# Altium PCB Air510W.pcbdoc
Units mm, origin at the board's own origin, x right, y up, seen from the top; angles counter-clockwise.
Board outline 24.2 x 23.82 mm, 4 copper layers (Top Layer, 内层 2, 内层 3, Bottom Layer); 1 components, 0 nets, 18 pads, 0 vias.
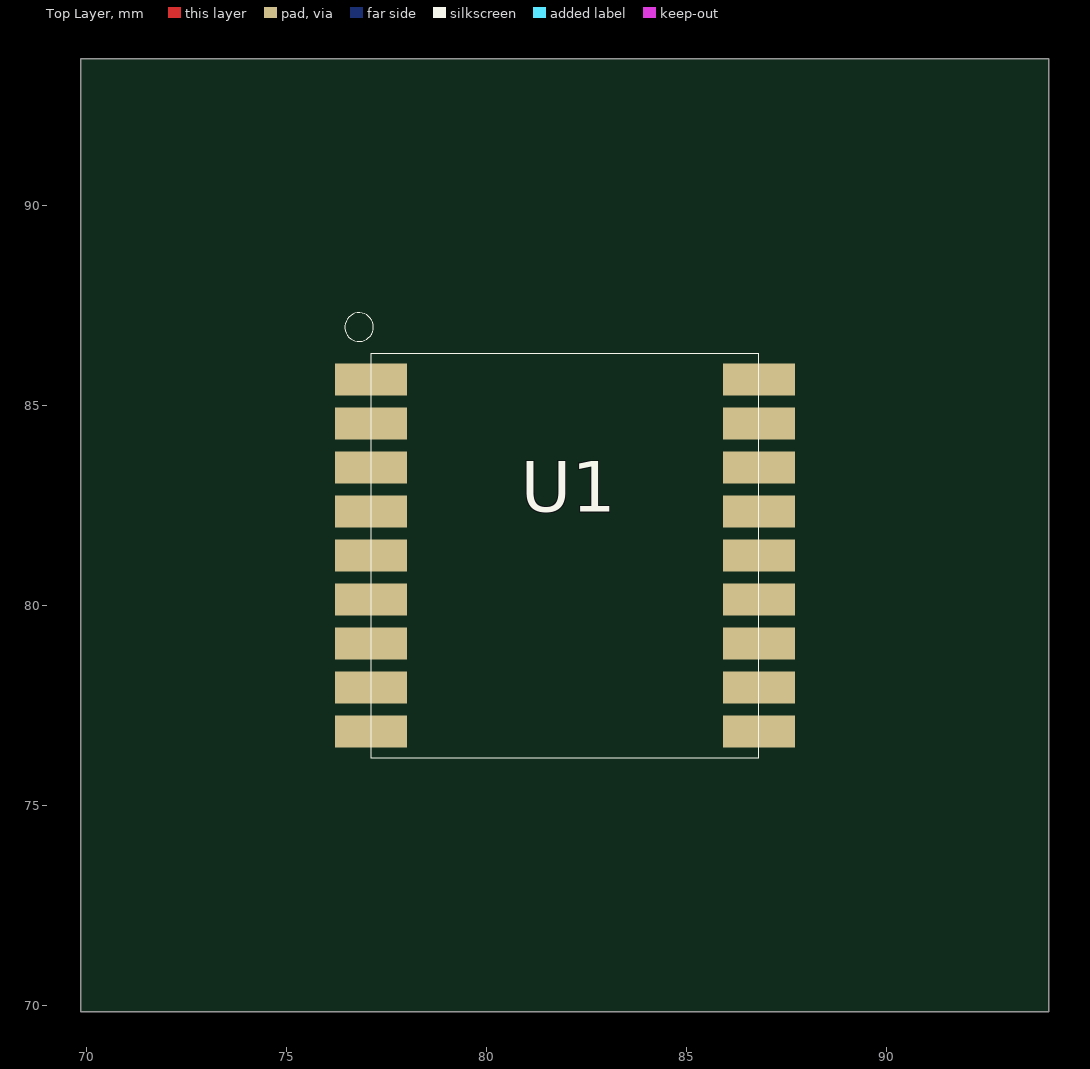
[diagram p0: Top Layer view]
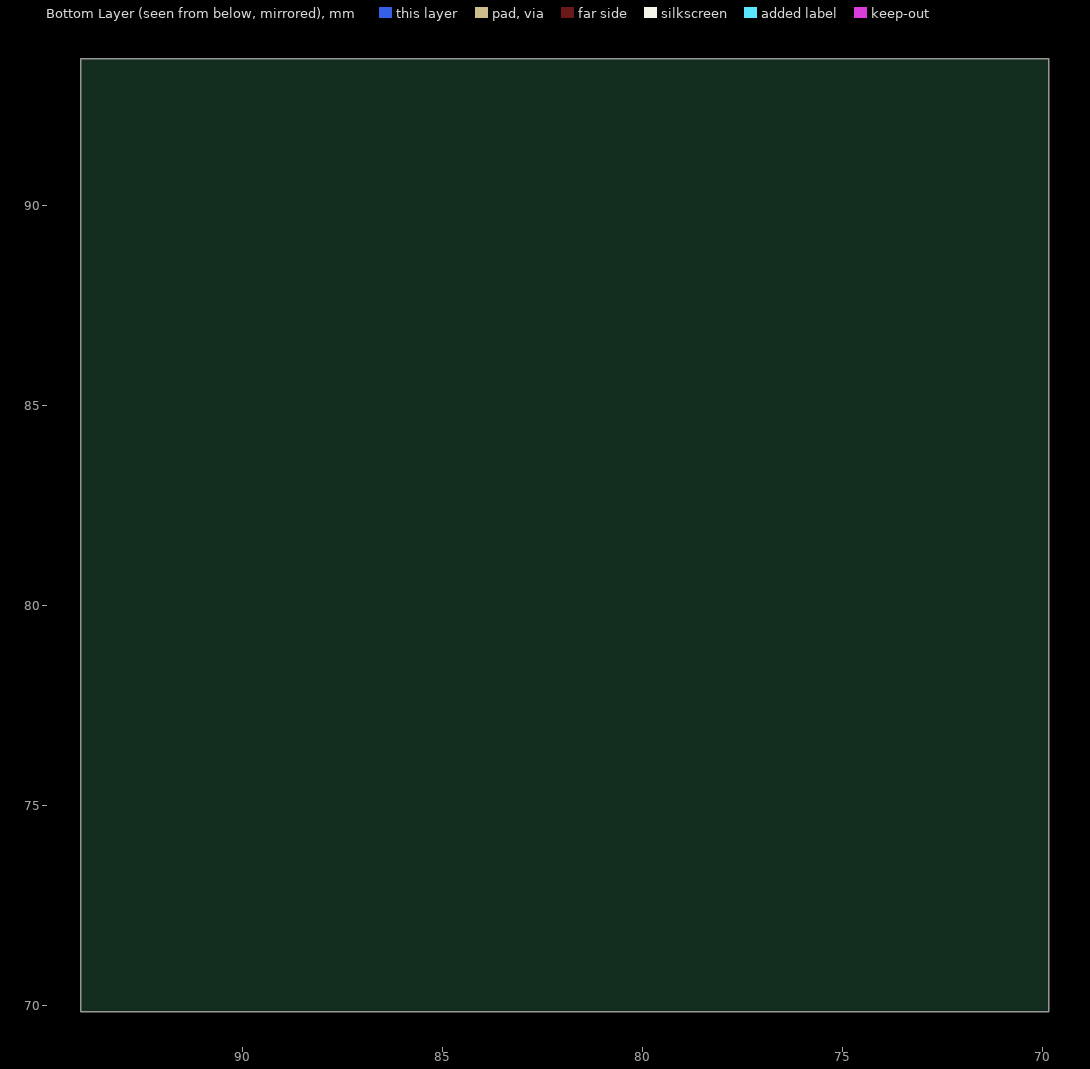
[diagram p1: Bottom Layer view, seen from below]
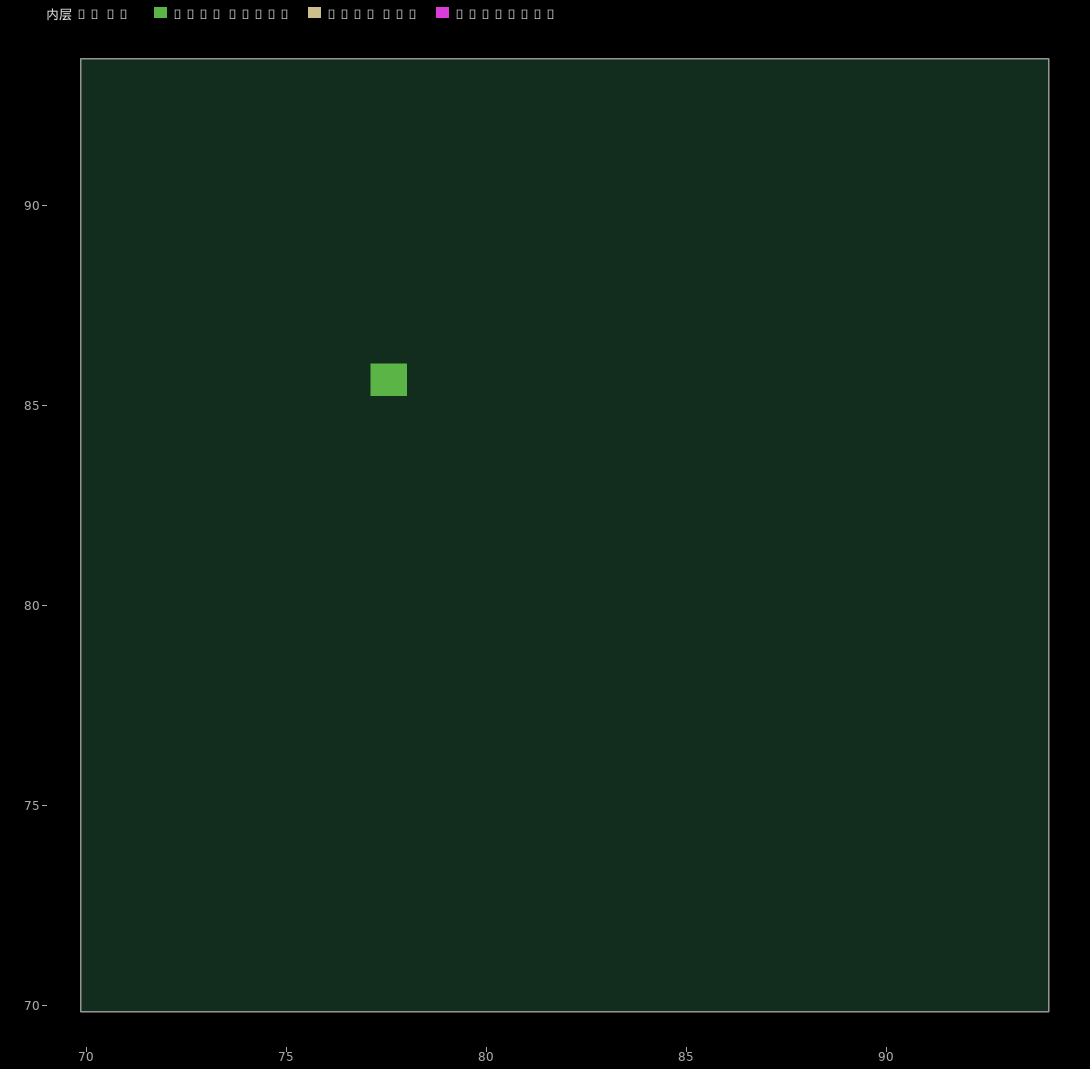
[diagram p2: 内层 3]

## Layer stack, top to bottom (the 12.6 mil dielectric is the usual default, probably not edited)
Top Layer: signal copper (thickness not stored)
Dielectric: dielectric 0.32, FR-4, Dk 4.8
内层 2: signal copper (thickness not stored)
Dielectric: dielectric 0.32, FR-4, Dk 4.8
内层 3: signal copper (thickness not stored)
Dielectric: dielectric 0.32, FR-4, Dk 4.8
Bottom Layer: signal copper (thickness not stored)

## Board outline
94.05,69.85 69.85,69.85 69.85,93.672 94.05,93.672

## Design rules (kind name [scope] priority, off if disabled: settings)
BoardOutlineClearance safeClearance [All] p0: genericclearance=0.254 ignorepadtopadclearanceinfootprint=FALSE except(0: Region-OutlineEdge Poly-OutlineEdge Text-OutlineEdge Sheet-OutlineEdge Hole-OutlineEdge Track-CutoutEdge SMDPad-CutoutEdge THPad-CutoutEdge Via-CutoutEdge Fill-CutoutEdge Region-CutoutEdge Poly-CutoutEdge Text-CutoutEdge Sheet-CutoutEdge Hole-CutoutEdge Arc-SplitContinuation Track-SplitContinuation SMDPad-SplitContinuation THPad-SplitContinuation Via-SplitContinuation Fill-SplitContinuation Poly-SplitContinuation Region-SplitContinuation Text-SplitContinuation; 0.152: Track-OutlineEdge SMDPad-OutlineEdge THPad-OutlineEdge Via-OutlineEdge Fill-OutlineEdge)
Clearance safeClearance [All] p1: gap=0.178 ignorepadtopadclearanceinfootprint=FALSE except(0: Region-Track Poly-Track Region-SMDPad Poly-SMDPad Region-THPad Poly-THPad Region-Via Poly-Via Region-Fill Poly-Fill Text-Fill Track-Region SMDPad-Region THPad-Region Via-Region Fill-Region Region-Region Poly-Region Text-Region Sheet-Region Hole-Region Track-Poly SMDPad-Poly THPad-Poly Via-Poly Fill-Poly Region-Poly Poly-Poly Text-Poly Sheet-Poly Hole-Poly Fill-Text Region-Text Poly-Text Text-Text Sheet-Text Hole-Text Region-Sheet Poly-Sheet Text-Sheet Sheet-Sheet Hole-Sheet Region-Hole Poly-Hole Text-Hole Sheet-Hole; 0.152: Track-Track SMDPad-Track THPad-Track Via-Track Fill-Track Text-Track Sheet-Track Hole-Track Track-SMDPad SMDPad-SMDPad THPad-SMDPad Via-SMDPad Fill-SMDPad Text-SMDPad Sheet-SMDPad Hole-SMDPad Track-THPad SMDPad-THPad THPad-THPad Via-THPad Fill-THPad Text-THPad Sheet-THPad Hole-THPad Track-Via SMDPad-Via THPad-Via Via-Via Fill-Via Text-Via Sheet-Via Hole-Via Track-Fill SMDPad-Fill THPad-Fill Via-Fill Fill-Fill Sheet-Fill Hole-Fill Track-Text SMDPad-Text THPad-Text Via-Text Track-Sheet SMDPad-Sheet THPad-Sheet Via-Sheet Fill-Sheet Track-Hole SMDPad-Hole THPad-Hole Via-Hole Fill-Hole Hole-Hole)
PasteMaskExpansion Common [All] p1: expansion=0
SolderMaskExpansion Common [All] p1: useseparateexpansions=TRUE expansion=0 expansionbottom=0
Width trackWidth [All] p1: maxlimit=12 minlimit=12 preferedwidth=12

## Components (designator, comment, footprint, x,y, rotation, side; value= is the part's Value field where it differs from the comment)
U1 "AIR510W" AIR510W 81.95,81.25 r0 top

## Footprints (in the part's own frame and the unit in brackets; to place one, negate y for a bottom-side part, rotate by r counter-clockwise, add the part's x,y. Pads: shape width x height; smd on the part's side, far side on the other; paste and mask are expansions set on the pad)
AIR510W [mm]
  rect 1.8x0.8 smd: 1(-4.85,4.4) 2(-4.85,3.3) 3(-4.85,2.2) 4(-4.85,1.1) 5(-4.85,0) 6(-4.85,-1.1) 7(-4.85,-2.2) 8(-4.85,-3.3) 9(-4.85,-4.4) 10(4.85,-4.4) 11(4.85,-3.3) 12(4.85,-2.2) 13(4.85,-1.1) 14(4.85,0) 15(4.85,1.1) 16(4.85,2.2) 17(4.85,3.3) 18(4.85,4.4)
  内层 3 region: -4.85,4.8 -3.95,4.8 -3.95,4 -4.85,4
  silkscreen extent -5.5,-5.05 4.85,6.07

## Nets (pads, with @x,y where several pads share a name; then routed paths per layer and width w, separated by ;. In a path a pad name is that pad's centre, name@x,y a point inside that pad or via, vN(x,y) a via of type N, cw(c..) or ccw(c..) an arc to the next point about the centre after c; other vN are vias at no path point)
pads on no net: U1.1 U1.2 U1.3 U1.4 U1.5 U1.6 U1.7 U1.8 U1.9 U1.10 U1.11 U1.12 U1.13 U1.14 U1.15 U1.16 U1.17 U1.18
